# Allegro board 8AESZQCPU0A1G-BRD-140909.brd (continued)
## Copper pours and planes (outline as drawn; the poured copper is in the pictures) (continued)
GND on BOTTOM: 126.51,58.74 125.79,59.46 120.02,59.46 119.13,60.35 119.13,62.76 119.79,63.42 125.12,63.42 125.75,64.05 125.75,70.61 122.44,70.61 122.44,72.1 122.91,72.58 127.4,72.58 127.4,65.35 127.67,65.08 127.66,65.07 127.66,63.95 128.29,63.95 128.29,59.25 127.78,58.74
GND on L2_GND: 89.72,1.02 88.82,1.92 88.82,7.33 88.49,8.42 87.61,9.14 86.26,9.14 85.14,8.03 85.14,7.42 84.88,7.16 84.88,1.92 84,1.04 15.72,1.04 15.72,15.41 16.51,16.21 16.51,18.67 16.43,18.75 1.45,18.75 1.02,19.18 1.02,72.78 208.98,72.78 208.98,1.02 105.92,1.02 105.92,10.54 104.01,12.45 100.08,12.45 99.06,11.43 99.06,10.67 98.68,10.29 98.68,1.02
GND on L4_GND, L9_GND, L11_GND: 89.72,1.02 88.82,1.92 88.82,7.33 88.49,8.42 87.61,9.14 86.26,9.14 85.14,8.03 85.14,7.42 84.88,7.16 84.88,1.92 84,1.04 15.72,1.04 15.72,15.41 16.51,16.21 16.51,18.67 16.43,18.75 1.45,18.75 1.02,19.18 1.02,72.78 208.98,72.78 208.98,1.02 105.92,1.02 105.92,10.54 104.01,12.45 100.08,12.45 99.06,11.43 99.06,10.67 98.42,10.03 98.42,1.02
V1P0 on TOP: 122.38,8.71 124.51,8.71 127.18,6.05 133.88,6.05 134.49,5.44 134.49,3.23 132.77,1.5 122.53,1.5 122.22,1.8 122.22,8.56
V1P0 on BOTTOM: 128.71,42.3 128.26,42.3 127.57,42.99 125.69,42.99 125.69,50.81 126.28,51.39 128.94,51.39 129.73,50.61 129.73,46.03 129.4,45.7 129.4,42.99 ; 1 cut-out
V1P0 on BOTTOM: 137.25,42 134.76,42 134.43,42.33 132.32,42.33 132.3,42.3 132.14,42.45 132.14,44.71 132.17,44.74 137.3,44.74 137.3,42.05
V1P0 on BOTTOM: 122.48,6.93 126.11,6.93 126.59,6.45 131.98,6.45 133.1,5.33 133.1,1.83 132.77,1.5 122.53,1.5 122.22,1.8 122.22,6.68
V1P0 on L5_SIG: 107.04,61.32 130.1,61.32 132.79,58.62 132.79,53.21 131.72,52.15 131.72,46.19 131.73,46.19 131.73,45.62 133.18,44.17 133.78,44.17 133.81,44.2 136.4,44.2 137.54,43.05 137.54,3.3 136.45,2.21 129.54,2.21 129.06,2.69 129.06,6.69 131.05,8.69 131.05,38.11 130.84,38.32 129.73,38.32 129.41,38 129.41,32.77 129.25,32.61 127.79,32.61 127.2,33.2 127.2,41.96 124.89,44.27 123.19,44.27 120.14,47.32 120.14,47.62 119.71,48.06 117.09,48.06 116.76,48.39 116.76,51.44 113.61,54.58 107.59,54.58 105.28,56.9 105.28,59.56
V1P0 on L8_SIG: 115.82,2.01 115.82,21.39 119.05,21.39 120.29,20.14 122.76,20.14 122.76,20.93 120.78,20.93 119.53,22.17 115.82,22.17 115.82,36.75 116.66,37.59 122.56,37.59 125.6,40.64 125.6,46.74 122.86,49.48 122.86,59.69 126.14,59.69 128.57,57.25 138.58,57.25 143.99,51.84 143.99,34.19 143,33.2 133.86,33.2 132.11,31.45 132.11,26.34 134.16,24.28 134.16,18.11 136.63,15.65 136.63,2.01
V1P0 on L10_SIG: 97.76,36.32 97.76,44.3 98.53,45.06 101.93,45.06 101.98,45.01 103.5,45.01 104.18,44.32 112.9,44.32 113.61,43.61 113.61,41.43 113.36,41.17 110.54,41.17 108.56,39.19 108.56,35.59 108,35.03 104.8,35.03 104.6,35.23 104.6,36.6 103.71,37.49 103.71,38.58 100.51,38.58 100.51,36.32 ; 1 cut-out
V1P1 on TOP: 80.72,28.63 82.32,28.63 84.28,26.67 87.2,26.67 87.55,26.31 87.55,22.68 87.4,22.53 86.11,22.53 84.63,24 82.85,24 82.55,23.7 80.8,23.7 80.44,24.05 80.44,28.35
V1P1 on BOTTOM: 130.63,36.75 130.39,36.99 130.39,39.48 130.7,39.79 132.07,39.79 132.75,39.1 132.75,37.88 131.63,36.75
V1P1 on BOTTOM: 80.87,28.63 82.32,28.63 84.48,26.47 87.4,26.47 87.78,26.09 87.78,22.94 87.38,22.53 86.11,22.53 84.4,24.23 83.13,24.23 82.83,23.93 80.54,23.93 80.44,24.03 80.44,28.19
V1P1 on L6_VCC: 85.85,34.16 126.47,34.16 129.54,37.24 129.54,38.13 129.64,38.23 132.59,38.23 132.79,38.02 132.79,35.89 130.28,33.38 130.28,26.01 129.03,24.77 115.95,24.77 115.06,23.88 101.42,23.88 100,25.3 92.99,25.3 90.25,22.56 85.19,22.56 84.94,22.81 84.94,33.25
V1P1_SW on TOP: 71.37,29.21 74.98,29.21 75.56,28.63 75.56,24.82 75.18,24.43 73.69,24.43 73.28,24.84 73.28,27.58 73.15,27.71 71.65,27.71 71.42,27.48 71.42,26.44 71.3,26.31 70.56,26.31 70.46,26.42 70.46,28.3
V1P5 on TOP: 80.49,16.31 81.51,16.31 81.56,16.26 81.56,15.85 82.04,15.37 83.64,15.37 83.85,15.16 83.85,13.03 83.31,12.5 81.76,12.5 81.46,12.8 81.46,14.58 81.25,14.78 80.8,14.78 80.49,15.09
V1P8 on TOP: 121.4,14.42 121.4,15.69 121.12,15.97 120.74,15.97 120.15,16.56 116.59,16.56 116.41,16.38 116.41,15.37 116.69,15.09 117.45,15.09 117.78,15.42 119.46,15.42 119.67,15.2 119.67,14.42
V1P8 on BOTTOM: 121.4,14.58 121.4,15.69 121.12,15.97 120.71,15.97 120.4,16.28 117.37,16.28 117.14,16.05 117.14,15.19 117.75,14.58
V1P8 on L5_SIG: 122.86,43.79 124.54,43.79 126.36,41.96 126.36,16 124.46,14.1 117.3,14.1 117.17,14.22 117.17,15.65 117.32,15.8 119.28,15.8 120.37,16.89 122.33,16.89 123.88,18.44 123.88,38.18 122.15,39.9 122.15,43.08
V1P8A on L3_SIG: 16.92,68.99 38.18,68.99 42.32,64.85 42.32,54.13 40.82,52.63 36.07,52.63 33.63,55.07 27.76,55.07 22.91,59.92 15.54,59.92 15.19,60.27 15.19,67.26
V1P35 on TOP: 120.03,18.7 120.03,17.32 119.52,16.81 116.87,16.81 116.53,17.15 116.53,17.28 116.53,17.28 116.53,18.15 117.07,18.7
V1P35 on BOTTOM: 120.09,18.55 120.09,16.59 120.07,16.56 119.13,16.56 118.87,16.81 116.84,16.81 116.53,17.13 116.53,17.72 116.84,18.03 118.16,18.03 118.83,18.7 119.94,18.7
V1P35 on L10_SIG: 128.52,30.99 133.3,35.76 133.3,42.24 132.49,43.05 130.33,43.05 116.15,28.88 116.15,28.19 116.18,28.22 116.18,15.77 116.71,15.24 126.49,15.24 128.52,17.27
V3P3 on TOP: 121.27,10.92 120.14,10.92 119.92,10.69 118.44,10.69 118.44,11.96 119.84,11.96 120.2,12.32 120.2,12.32 121.36,12.32 121.43,12.25 121.43,11.07
V3P3 on TOP: 122.28,18.72 123.37,18.72 124.1,17.98 124.1,16.56 123.95,16.41 122.48,16.41 122.28,16.61
V3P3 on TOP: 12.34,25.76 29.36,25.76 30.07,26.47 33.15,26.47 33.81,25.81 33.81,21.64 31.14,18.97 12.88,18.97 11.73,20.12 11.73,25.15
V3P3 on TOP: 80.52,18.77 82.5,18.77 82.55,18.82 83.72,18.82 83.95,19.05 83.95,20.45 83.72,20.68 81.97,20.68 81.56,20.27 81.56,20.04 81.43,19.91 80.7,19.91 80.52,19.74
V3P3 on BOTTOM: 18.67,25.76 29.36,25.76 30.07,26.47 33.15,26.47 33.81,25.81 33.81,21.64 31.14,18.97 18.34,18.97 17.83,19.48 17.83,24.92
V3P3 on BOTTOM: 122.33,18.67 123.17,18.67 124,17.86 124.13,17.7 124.13,16.48 123.93,16.28 122.61,16.28 122.2,16.69 122.2,18.54
V3P3 on L7_VCC: 96.95,2.03 90.14,2.03 89.83,2.34 89.83,6.63 89.61,6.85 89.61,6.86 89.18,7.29 88.82,7.29 88.75,7.37 88.75,8.36 87.96,9.14 86.26,9.14 85.01,7.9 85.01,6.33 83.87,5.18 83.87,2.34 83.56,2.03 16.74,2.03 16.74,18.54 16.51,18.77 5.51,18.77 4.95,19.33 4.95,35.41 6.65,37.11 35.53,37.11 38.33,34.32 38.33,13.13 40.94,10.52 53.7,10.52 55.02,11.84 62.13,11.84 69.06,18.77 74.17,18.77 75.26,19.86 79.02,19.86 79.11,19.77 81.09,19.77 84.1,22.78 84.1,33.4 84.71,34.01 84.71,40.69 85.04,41.02 95.81,41.02 96.67,41.88 96.67,54 97.26,54.58 126.62,54.58 126.62,23.67 124.18,21.23 124.18,17.04 123.49,16.36 122.99,16.36 122.68,16.05 122.68,15.82 121.08,15.82 118.92,13.67 118.92,11.02 118.08,10.19 109.19,10.19 108.92,10.46 108.92,12.7 107.31,14.3 98.91,14.3 97.92,13.31 95.53,13.31 94.72,12.5 94.72,10.77 95,10.49 95,6.6 95.73,5.87 96.65,5.87 96.95,5.56
V3P3_CLKBUF_VDD on BOTTOM: 94.34,35.33 101.24,35.33 102.34,34.24 102.34,28.52 101.07,27.25 97.18,27.25 96.93,27.51 96.93,28.45 96.65,28.73 93.34,28.73 93.04,29.03 93.04,34.04
V3P3_SPI on L5_SIG: 29.11,40.34 37.44,40.34 37.74,40.03 37.74,33.45 37.31,33.02 29.92,33.02 28.7,34.24 28.7,39.93
V3P3A on TOP: 71.88,71.88 72.77,71.88 73.28,71.37 73.28,66.67 71.63,66.67 71.63,71.63
V3P3A on BOTTOM: 49.78,32.46 50.88,32.46 51.08,32.26 51.08,29.57 50.88,29.36 49.91,29.36 49.66,29.62 49.66,32.33
V3P3A on BOTTOM: 125.75,69.85 125.75,67.89 125.62,67.76 124.48,67.76 124.1,68.14 123.21,68.14 123.21,69.74 123.32,69.85
V3P3A on L6_VCC: 28.37,27 25.48,29.9 25.48,42.19 24.1,43.56 7.37,43.56 6.15,44.78 6.15,70.41 7.7,71.96 57.47,71.96 60.6,68.8 63.73,71.96 72.85,71.96 73.43,71.37 73.43,68.07 68.22,62.87 68.22,50.37 66.95,49.1 61.37,49.1 60.38,48.11 60.38,35.05 60.48,34.95 60.48,28.32 59.16,27
V3P3A on L10_SIG: outline of 91 points within 32.49,2.16 207.14,71.75 ; 4 cut-outs
V5A on TOP: 59.69,22.3 61.98,22.3 62.84,21.44 67.34,21.44 67.67,21.11 67.67,18.26 66.8,17.4 65.53,17.4 64.14,18.8 59.84,18.8 59.54,19.1 59.54,22.15
V5A on TOP: 64.74,64.85 67.44,64.85 68.48,63.8 68.48,62 68,61.52 64.97,61.52 64.44,62.05 64.44,64.54
V5A on TOP: 122.14,12.31 122.14,11.27 121.98,10.99 122.08,10.7 122.08,10.12 121.7,9.74 121.7,9.07 121.81,8.97 123.14,8.97 123.29,9.12 123.29,11.03 123.23,11.09 122.64,11.09 122.44,11.3 122.44,12.31
V5A on TOP, BOTTOM: 62.66,40.44 64.57,40.44 65.15,39.85 65.15,39.04 64.77,38.66 63.98,38.66 63.6,38.28 62.66,38.28 62.08,38.86 62.08,39.85
V5A on BOTTOM: 62.03,21.44 67.34,21.44 67.44,21.34 67.44,18.03 66.8,17.4 65.66,17.4 64.41,18.64 61.62,18.64 61.47,18.8 61.47,20.88
V5A on BOTTOM: 64.74,64.85 66.52,64.85 67.08,64.29 67.08,61.52 64.97,61.52 64.44,62.05 64.44,64.54
V5A on L7_VCC: 107.26,5.03 107.26,9.14 107.72,9.6 118.72,9.6 119.51,10.39 119.51,13.59 121.03,15.11 123.32,15.11 124.61,16.41 124.61,20.9 127.41,23.7 127.41,54.28 126.21,55.47 96.67,55.47 95.43,54.23 95.43,42.57 94.92,42.06 84.18,42.06 83.49,41.38 83.49,23.52 80.52,20.55 74.65,20.55 73.53,19.43 68.55,19.43 61.49,12.37 54.43,12.37 53.34,11.28 41.71,11.28 39.17,13.82 39.17,35.51 36.86,37.82 6.27,37.82 4.95,39.14 4.95,71.58 57.44,71.58 60.55,68.7 63.67,71.58 117.63,71.58 118.52,70.69 118.52,66.7 120.22,65 130.43,65 132.64,62.79 132.64,30.28 131.93,29.57 131.93,27.38 133.99,25.32 133.99,18.59 135.97,16.61 135.97,2.84 135.13,2.01 110.29,2.01
V12A on TOP: 43.56,14.86 43.56,24.13 43.18,24.51 40.39,24.51 39.75,23.88 39.75,14.61 40.01,14.35 43.05,14.35
V12A on TOP: 71.55,38.96 67.97,38.96 67.87,38.86 67.87,35.28 68.02,35.13 68.61,35.13 69.02,34.71 71.78,34.71 71.96,34.89 71.96,38.56
V12A on TOP: 16.36,11.86 21.59,11.86 22.48,12.75 25.63,12.75 25.93,12.45 25.93,10.06 25.1,9.22 18.39,9.22 16.71,7.54 16,7.54 15.7,7.85 15.7,11.2
V12A on TOP: 14.99,42.42 14.99,40.01 15.11,39.88 18.21,39.88 18.92,39.17 24.18,39.17 24.94,39.93 24.94,42.42 23.19,44.17 17.5,44.17 17.02,43.69 17.02,42.67 16.76,42.42
V12A on TOP: 62.13,27.91 68.96,27.91 69.44,27.43 69.44,26.11 68.66,25.32 61.62,25.32 61.37,25.58 61.37,27.15
V12A on TOP: 98.68,10.54 98.68,6.32 96.06,6.32 96.06,7.26 95.63,7.7 95.63,10.67 95.2,11.1 95.2,11.96 97.1,11.96 100.42,15.28 102.48,15.28 103.25,16.05 106.76,16.05 107.19,15.62 107.19,12.22 106.93,11.96 105,11.96 104.65,12.32 100.46,12.32
V12A on TOP: 61.58,45.05 60.55,46.08 60.55,51.03 60.83,51.31 65.18,51.31 65.28,51.21 65.28,45.49 64.82,45.04 64.82,43.49 64.77,43.43 62.74,43.43 62.61,43.56 62.61,44.47 62.03,45.05
V12A on TOP: 93.83,71.63 99.9,71.63 100.84,70.69 100.84,69.37 100.58,69.11 98.98,69.11 98.09,70 97.1,70 96.24,69.14 96.24,67.36 95.83,66.95 93.6,66.95 93.42,67.13 93.42,71.22
V12A on BOTTOM: 41.4,18.67 44.2,18.67 44.45,18.41 44.45,16.13 44.32,16 41.53,16 41.15,16.38 41.15,18.41
V12A on BOTTOM: 96.34,8.05 97.41,8.05 98.63,6.83 98.63,6.38 98.5,6.25 96.32,6.25 96.11,6.45 96.11,7.82
V12A on BOTTOM: 62.13,27.91 68.96,27.91 69.44,27.43 69.44,26.11 68.66,25.32 61.09,25.32 61.04,25.37 61.04,26.82
V12A on BOTTOM: 71.25,38.96 67.89,38.96 67.87,38.94 67.87,35.28 68.2,34.95 68.78,34.95 69.02,34.71 71.78,34.71 71.96,34.89 71.96,38.25
V12A on BOTTOM: 60.31,45.05 60.12,45.24 60.12,47.73 63.45,51.05 64.85,51.05 64.95,50.95 64.95,45.16 64.82,45.03 64.82,44.78 64.82,44.78 64.82,43.15 64.57,42.89 62.67,42.89 62.54,43.02 62.54,44.54 62.03,45.05
V12A on BOTTOM: 94.21,71.98 100.15,71.98 100.84,71.3 100.84,69.37 100.58,69.11 98.98,69.11 98.09,70 97.1,70 96.24,69.14 96.24,67.36 95.83,66.95 93.7,66.95 93.42,67.23 93.42,71.2
V12A on L6_VCC: 107.44,1.75 127.1,1.75 129.82,4.47 129.82,23.72 129.16,24.38 116.08,24.38 115.27,23.57 101.19,23.57 99.8,24.97 93.32,24.97 90.14,21.79 84.99,21.79 84.2,22.58 84.2,55.52 93.29,64.62 132.18,64.62 134.24,66.67 134.24,71.3 133.99,71.55 78.33,71.55 68.73,61.95 68.73,49.91 67.36,48.54 63.6,48.54 63.55,48.59 61.49,48.59 60.93,48.03 60.93,33.43 60.99,33.38 60.99,27.48 59.66,26.16 28.07,26.16 24.92,29.31 24.92,41.86 23.85,42.93 6.99,42.93 5.54,41.48 5.54,20.62 8.99,17.17 15.54,17.17 16.23,16.48 16.23,3.71 18.24,1.7 82.6,1.7 84.63,3.73 84.63,8.2 85.45,9.02 89.61,9.02 92.13,6.5 97.1,6.5 97.46,6.86 97.46,10.36 99.67,12.57 104.19,12.57 106.71,10.06 106.71,2.49
V12A on L7_VCC: 98.35,10.77 98.35,6.32 96.06,6.32 96.06,7.26 95.63,7.7 95.63,10.67 95.2,11.1 95.2,11.96 97.31,11.96 99.11,13.77 107.09,13.77 107.21,13.64 107.21,12.29 106.86,11.94 104.83,11.94 104.19,12.57 100.15,12.57
V12A_PM_V1P0 on TOP: 109.86,13.72 116.2,13.72 116.97,12.95 116.97,9.78 116.46,9.27 114.05,9.27 113.92,9.4 113.92,11.3 113.54,11.68 110.11,11.68 109.35,12.45 109.35,13.21
VCCP on TOP: 76.64,45.51 76.64,43.02 78.05,41.61 91.9,41.61 92.56,42.27 92.56,47.9 91.49,48.97 71.58,48.97 71.48,48.87 71.48,47.6 72.24,46.84 75.31,46.84
VCCP on BOTTOM: 82.83,42.29 83.57,42.29 84.3,41.55 91.85,41.55 92.56,42.27 92.56,47.96 91.54,48.97 71.58,48.97 71.45,48.84 71.45,47.6 72.21,46.84 75.31,46.84 76.25,45.9 81.97,45.9 82.55,45.31 82.55,42.57
VCCP on L6_VCC: 93.83,64.06 85.06,55.3 85.06,42.39 85.75,41.71 91.72,41.71 94.21,44.2 123.09,44.2 125.73,41.55 125.73,39.14 126.14,38.73 132.72,38.73 133.35,38.1 133.35,35.61 133.88,35.08 152.76,35.08 153.39,35.71 153.39,43.1 151.82,44.68 133.65,44.68 131.62,46.71 131.62,51.94 132.69,53.01 132.69,63.8 132.44,64.06 ; 1 cut-out
VDDQ_CPU_DDR on TOP: 115.09,70.54 119.79,70.54 120.19,70.94 120.19,71.88 120.17,71.91 120.78,72.52 121.72,72.52 122.1,72.14 122.1,71.3 122.07,71.27 122.07,70.38 122.76,69.7 122.76,67.11 122.33,66.67 115.24,66.67 114.91,67.01 114.91,70.36
VDDQ_CPU_DDR on TOP: 128.6,72.29 130.84,72.29 131.22,71.91 131.22,68.22 131.01,68.02 128.88,68.02 128.47,68.43 128.47,72.16
VDDQ_CPU_DDR on BOTTOM: 127.86,68.22 131.11,68.22 131.11,72 127.86,72
VDDQ_CPU_DDR on BOTTOM: 115.29,69.65 118.21,69.65 120.45,71.88 120.45,72.19 120.78,72.52 121.72,72.52 122.1,72.14 122.1,71.3 122.07,71.27 122.07,70.38 122.76,69.7 122.76,67.11 122.33,66.67 114.81,66.67 114.43,67.06 114.43,68.78
VDDQ_CPU_DDR on L6_VCC: 207.54,71.75 208,71.3 208,3.73 205.41,1.14 132.87,1.14 130.99,3.02 130.99,32.87 132.77,34.65 152.93,34.65 153.95,35.66 153.95,44.15 153.01,45.09 133.83,45.09 132,46.91 132,51.74 133.53,53.26 133.53,64.85 135.23,66.55 135.23,71.42 135.56,71.75
VDDQ_CPU_DDR on L7_VCC: 139.55,1.14 136.65,4.04 136.65,17.68 134.72,19.61 134.72,25.27 132.33,27.66 132.33,29.36 133.38,30.4 133.38,63.02 130.84,65.56 120.78,65.56 119.58,66.75 119.58,71.17 120.17,71.75 207.54,71.75 208,71.3 208,3.73 205.41,1.14 ; 1 cut-out
SW_VNN on TOP: 68.17,33.8 68.17,33.07 68.82,32.42 74.24,32.42 74.24,32.44 74.5,32.44 74.85,32.79 74.85,37.52 74.45,37.92 72.72,37.92 72.29,37.49 72.29,34.74 71.88,34.33 70.09,34.33 70.08,34.31 70.08,33.88 70.04,33.85 68.22,33.85
VNN on TOP: 78.26,33.78 88.85,33.78 88.87,33.76 89.64,33.76 91.52,35.64 91.52,39.73 90.75,40.49 85.72,40.49 85.57,40.34 85.57,39.73 85.34,39.5 83.82,39.5 83.82,37.59 83.69,37.47 81.99,37.47 81.79,37.67 78.23,37.67 78.03,37.47 78.03,34.01
VNN on BOTTOM: 134.15,42.22 125.18,42.22 124.9,41.94 124.9,41.49 124.92,41.47 124.92,37.87 125.34,37.45 130.03,37.45 130.21,37.63 130.21,40.04 131.33,41.16 133.18,41.16 133.72,41.69 134.3,41.69 134.3,42.07
VNN on BOTTOM: 84.45,33.78 89.69,33.78 91.52,35.61 91.52,39.75 90.78,40.49 84,40.49 82.32,38.81 82.32,38 81.99,37.67 78.23,37.67 78.03,37.47 78.03,34.44 78.05,34.44 78.36,34.14 84.1,34.14
VNN on L3_SIG: 126.11,36.37 124.94,37.54 124.94,39.04 125.65,39.75 125.65,41 125.2,41.45 125.2,41.84 125.43,42.07 128.92,42.07 129.4,41.59 129.4,40.7 130.32,39.79 132.23,39.79 132.63,40.18 132.63,41.28 132.52,41.39 130.64,41.39 130.31,41.72 130.31,42.22 130.44,42.35 134.26,42.35 134.26,36.68 133.96,36.37
VNN on L6_VCC: 94.49,43.69 91.62,40.82 86.11,40.82 85.7,40.41 85.7,35.51 86.18,35.03 126.75,35.03 129.08,37.36 129.08,38.13 128.88,38.33 125.81,38.33 125.37,38.76 125.37,41.3 122.99,43.69
VTT_CPU_DDR on BOTTOM: 127.81,67.13 127.81,65.34 127.96,65.19 128.6,65.19 128.6,59.17 128.62,59.15 130.63,59.15 130.63,66.49 129.99,67.13
VTT_CPU_DDR on L8_SIG: 137.59,71.75 203.17,71.75 205.69,69.24 205.69,66.24 204.27,64.82 141.94,64.82 136.8,59.69 129.41,59.69 128.93,60.17 128.93,65.1 129.36,65.53 131.37,65.53
N17058814 on TOP: 50.42,22.48 55.12,22.48 55.42,22.17 55.42,19.99 55.24,19.81 53.54,19.81 52.98,20.37 51.33,20.37 51.26,20.29 51.26,18.64 51.13,18.52 50.39,18.52 50.24,18.67 50.24,22.3
N17060112 on TOP: 14.94,34.98 17.98,34.98 17.98,34.72 17.78,34.52 17.78,34.19 17.7,34.11 17.17,34.11 16.99,33.93 16.99,32.69 17.12,32.56 17.7,32.56 17.78,32.49 17.78,28.85 17.4,28.47 13.69,28.47 13.34,28.83 13.34,32.38 13.59,32.64 14.1,32.64 14.27,32.82 14.27,34.01 14.86,34.59 14.86,34.9
N17152659 on TOP: 71.55,40.21 67.87,40.21 67.36,40.71 67.36,45.29 67.74,45.67 71.73,45.67 72.47,44.93 72.47,41.12
N17152659 on L3_SIG: 69.41,42.17 69.42,42.17 67.62,40.36 63.07,40.36 61.9,41.53 61.9,42.88 61.59,43.18 61.59,45.49 61.8,45.69 69.13,45.69 69.57,45.25 69.57,42.33
N17167679 on TOP: 62.15,30.63 61.87,30.91 61.87,32.54 62.41,33.07 62.41,35.56 62.94,36.09 64.26,36.09 64.47,35.89 64.47,34.11 64.72,33.86 64.72,30.63 ; 1 cut-out
N17168118 on TOP: 83.68,65.71 83.68,65.48 83.63,65.43 82.38,65.43 82.05,65.1 82.05,64.64 81.19,63.78 78.32,63.78 78.17,63.93 78.17,64.49 78.32,64.64 81.29,64.64 81.37,64.72 81.37,65.12 82.03,65.78 83.6,65.78
N17180842 on TOP: 113.75,8.96 119.48,8.96 119.79,8.66 119.79,1.83 119.38,1.42 117.4,1.42 116.94,1.88 116.94,7.18 113.64,7.18 113.64,8.86
N17255975 on TOP: 103.4,70.28 109.19,70.28 109.73,69.75 109.73,66.6 108.86,65.74 103.45,65.74 103.12,66.07 103.12,70
N17799133 on L3_SIG: 117.46,27.15 117.46,31.25 112.86,31.25 112.86,25.79 116.1,25.79

Small or netless copper shapes (teardrops, artwork), in the pictures only: 1 on TOP

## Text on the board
User.Comments: PARTITION_2
Ref Des/Silkscreen Top: AESZQCPU
User.25: FIGURE | SIZE | 10.0 | 15.0 | 20.0 | 43.0 | 71.0 | 126.0 | 40.0 | 63.0 | 100.0x40.0 | DRILL CHART: TOP to BOTTOM | ALL UNITS ARE IN MILS | TOLERANCE | +3.0/-3.0 | +2.0/-2.0 | PLATED | NON-PLATED | QTY | 2562 | 10 | 302 | 7 | 2 | 4
